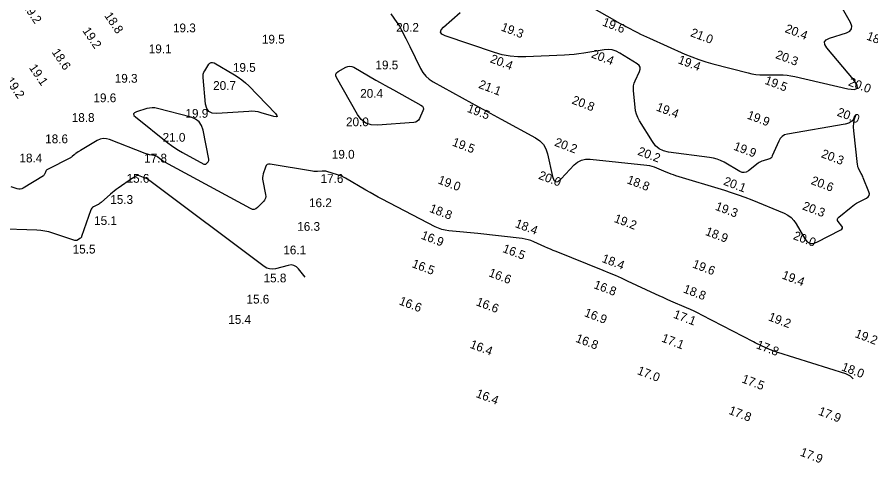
# Model space of a CAD drawing. Extents: x 824616 to 827440, y 158441 to 163197.
# Drawn here: x 826605.2 to 827092.4, y 159619.4 to 159873.5 of the extents above; entities that cross this region are included whole.
import ezdxf

# ---------------------------------------------------------------- set-up
doc = ezdxf.new("R2010")
doc.units = 0
for name, color, linetype in [('V-CHAN-CONT-EL16', 7, 'Continuous'), ('V-CHAN-CONT-EL18', 7, 'Continuous'), ('V-CHAN-CONT-EL20', 7, 'Continuous'), ('V-TOPO-SOUN', 7, 'Continuous')]:
    doc.layers.add(name, color=color, linetype=linetype)

msp = doc.modelspace()

# ---------------------------------------------------------------- linework, layer by layer
at = {"layer": 'V-CHAN-CONT-EL16'}
msp.add_lwpolyline([(826769.52, 159725.22), (826765.77, 159730.04), (826764.54, 159731.26), (826763.16, 159732), (826761.61, 159732.25), (826759.89, 159732.02), (826752.71, 159730.11), (826750.95, 159729.84), (826749.27, 159729.96), (826747.67, 159730.47), (826746.15, 159731.39), (826680.92, 159780.28), (826680.29, 159780.72), (826679.63, 159781.12), (826678.96, 159781.46), (826678.25, 159781.77), (826674.57, 159783.2), (826674.26, 159783.29), (826673.97, 159783.3), (826673.67, 159783.24), (826673.39, 159783.11), (826672.26, 159782.45), (826671.98, 159782.28), (826671.7, 159782.1), (826671.42, 159781.92), (826671.15, 159781.74), (826662.92, 159776.01), (826661.78, 159775.19), (826660.67, 159774.34), (826659.57, 159773.47), (826658.5, 159772.56), (826653.1, 159767.85), (826652.62, 159767.46), (826652.11, 159767.09), (826651.59, 159766.76), (826651.04, 159766.47), (826648.81, 159765.34), (826648.29, 159765.02), (826647.86, 159764.62), (826647.53, 159764.14), (826647.28, 159763.59), (826642.04, 159748.49), (826641.88, 159748.13), (826641.67, 159747.81), (826641.41, 159747.53), (826641.09, 159747.3), (826639.71, 159746.45), (826639.37, 159746.28), (826639.01, 159746.19), (826638.64, 159746.19), (826638.26, 159746.27), (826625.61, 159750.41), (826623.36, 159751.07), (826621.08, 159751.56), (826618.78, 159751.89), (826616.44, 159752.06), (826593.19, 159752.93)], dxfattribs=at)
at = {"layer": 'V-CHAN-CONT-EL18'}
msp.add_lwpolyline([(827082.22, 159667.32), (827080.8, 159668.89), (827077.96, 159670.24), (827039.28, 159682.33), (827038.07, 159682.73), (827036.88, 159683.16), (827035.69, 159683.62), (827034.52, 159684.11), (827029.87, 159686.16), (827028.71, 159686.68), (827027.55, 159687.22), (827026.41, 159687.78), (827025.28, 159688.36), (826995.94, 159703.69), (826993.78, 159704.79), (826991.6, 159705.86), (826989.4, 159706.87), (826987.18, 159707.85), (826978.27, 159711.68), (826976.04, 159712.65), (826973.82, 159713.63), (826971.61, 159714.63), (826969.41, 159715.65), (826953.43, 159723.1), (826950.02, 159724.66), (826946.59, 159726.17), (826943.14, 159727.64), (826939.68, 159729.06), (826912.76, 159739.87), (826911.14, 159740.53), (826909.54, 159741.2), (826907.94, 159741.89), (826906.34, 159742.6), (826899.99, 159745.46), (826898.38, 159746.11), (826896.74, 159746.63), (826895.06, 159747.02), (826893.35, 159747.28), (826868.08, 159750.12), (826866.01, 159750.34), (826863.95, 159750.56), (826861.88, 159750.77), (826859.82, 159750.96), (826851.55, 159751.72), (826849.51, 159752.01), (826847.53, 159752.49), (826845.6, 159753.16), (826843.74, 159754.02), (826813.6, 159769.72), (826811.24, 159770.96), (826808.89, 159772.24), (826806.57, 159773.54), (826804.26, 159774.87), (826792.64, 159781.66), (826791.52, 159782.27), (826790.38, 159782.81), (826789.2, 159783.28), (826787.99, 159783.67), (826781.98, 159785.45), (826781.31, 159785.62), (826780.64, 159785.72), (826779.96, 159785.77), (826779.28, 159785.75), (826776.53, 159785.56), (826775.84, 159785.53), (826775.15, 159785.54), (826774.47, 159785.59), (826773.79, 159785.69), (826749.61, 159789.66), (826748.68, 159789.68), (826747.92, 159789.42), (826747.34, 159788.87), (826746.94, 159788.03), (826745.66, 159784.11), (826745.41, 159783.13), (826745.29, 159782.13), (826745.29, 159781.14), (826745.43, 159780.13), (826746.96, 159772.46), (826747.06, 159771.31), (826746.89, 159770.25), (826746.45, 159769.26), (826745.73, 159768.36), (826742.32, 159764.91), (826741.44, 159764.23), (826740.5, 159763.9), (826739.52, 159763.94), (826738.48, 159764.34), (826689.57, 159790.79), (826689.03, 159791.1), (826688.51, 159791.43), (826688, 159791.78), (826687.51, 159792.15), (826685.58, 159793.69), (826685.08, 159794.04), (826684.54, 159794.32), (826683.98, 159794.52), (826683.39, 159794.65), (826680.81, 159795.07), (826680.18, 159795.18), (826679.56, 159795.33), (826678.95, 159795.52), (826678.35, 159795.73), (826658, 159803.68), (826656.18, 159804.18), (826654.4, 159804.26), (826652.65, 159803.9), (826650.93, 159803.12), (826641.42, 159797.53), (826641.08, 159797.33), (826640.75, 159797.12), (826640.43, 159796.91), (826640.11, 159796.69), (826638.72, 159795.72), (826638.46, 159795.54), (826638.2, 159795.34), (826637.95, 159795.14), (826637.7, 159794.93), (826636.72, 159794.08), (826636.47, 159793.87), (826636.21, 159793.69), (826635.94, 159793.52), (826635.66, 159793.36), (826622.51, 159786.72), (826622.2, 159786.53), (826621.95, 159786.29), (826621.74, 159786), (826621.59, 159785.67), (826621.1, 159784.25), (826620.95, 159783.91), (826620.76, 159783.62), (826620.51, 159783.36), (826620.22, 159783.14), (826608.64, 159775.99), (826607.86, 159775.6), (826607.04, 159775.41), (826606.21, 159775.41), (826605.35, 159775.6), (826601.88, 159776.73)], dxfattribs=at)
at = {"layer": 'V-CHAN-CONT-EL20'}
for points in [[(826928.5, 159881.59), (826946.03, 159871.75), (826947.67, 159870.84), (826949.31, 159869.94), (826950.96, 159869.05), (826952.61, 159868.18), (826959.25, 159864.72), (826960.92, 159863.87), (826962.6, 159863.04), (826964.29, 159862.24), (826965.99, 159861.47), (826986.27, 159852.45), (826990.16, 159850.82), (826994.1, 159849.35), (826998.09, 159848.05), (827002.15, 159846.91), (827022.31, 159841.69), (827024.49, 159841.2), (827026.68, 159840.85), (827028.89, 159840.65), (827031.12, 159840.6), (827040.08, 159840.66), (827042.31, 159840.62), (827044.53, 159840.44), (827046.73, 159840.13), (827048.92, 159839.69), (827079.27, 159832.7), (827082.97, 159832.22), (827084.74, 159832.93), (827084.56, 159834.82), (827082.44, 159837.9), (827067.17, 159856.07), (827066.05, 159857.86), (827065.94, 159859.35), (827066.83, 159860.56), (827068.74, 159861.47), (827078.37, 159864.53), (827080.33, 159865.47), (827081.36, 159866.77), (827081.49, 159868.43), (827080.7, 159870.45), (827070.98, 159887.58)], [(826818.41, 159875.36), (826821.9, 159870.54), (826822.65, 159869.47), (826823.36, 159868.36), (826824.02, 159867.23), (826824.63, 159866.07), (826827.01, 159861.38), (826827.6, 159860.21), (826828.19, 159859.03), (826828.77, 159857.86), (826829.35, 159856.68), (826835.41, 159844.21), (826836.76, 159841.89), (826838.41, 159839.84), (826840.37, 159838.09), (826842.62, 159836.62), (826864.62, 159824.51), (826868.8, 159822.21), (826872.98, 159819.92), (826877.17, 159817.64), (826881.37, 159815.37), (826901.05, 159804.75), (826903.54, 159803.07), (826905.51, 159800.99), (826906.95, 159798.52), (826907.87, 159795.67), (826910.69, 159782.65), (826911.43, 159780.57), (826912.48, 159779.65), (826913.86, 159779.89), (826915.56, 159781.3), (826923, 159789.23), (826924.96, 159790.93), (826927.14, 159792.06), (826929.52, 159792.62), (826932.12, 159792.61), (826964.5, 159789.09), (826965.94, 159788.88), (826967.35, 159788.56), (826968.73, 159788.14), (826970.08, 159787.61), (826975.43, 159785.28), (826976.78, 159784.72), (826978.14, 159784.2), (826979.51, 159783.72), (826980.9, 159783.28), (827008.77, 159774.84), (827012.71, 159773.6), (827016.62, 159772.26), (827020.5, 159770.83), (827024.34, 159769.3), (827042.77, 159761.74), (827044.9, 159760.67), (827046.78, 159759.29), (827048.4, 159757.62), (827049.76, 159755.65), (827054.69, 159747.18), (827056.05, 159745.47), (827057.63, 159744.57), (827059.46, 159744.48), (827061.51, 159745.19), (827075.25, 159752.27), (827075.83, 159752.69), (827076.1, 159753.18), (827076.07, 159753.73), (827075.72, 159754.36), (827073.71, 159757.01), (827073.35, 159757.66), (827073.27, 159758.27), (827073.49, 159758.85), (827073.98, 159759.4), (827081.03, 159765.24), (827082.03, 159766.03), (827083.08, 159766.77), (827084.17, 159767.44), (827085.29, 159768.05), (827089.86, 159770.39), (827090.8, 159771.05), (827091.34, 159771.86), (827091.47, 159772.83), (827091.19, 159773.94), (827087.96, 159781.99), (827087.69, 159782.62), (827087.41, 159783.25), (827087.11, 159783.86), (827086.8, 159784.47), (827085.5, 159786.89), (827085.21, 159787.51), (827084.98, 159788.14), (827084.82, 159788.79), (827084.71, 159789.46), (827082.62, 159808.76), (827082.5, 159811.03), (827082.65, 159813.26), (827083.07, 159815.47), (827083.74, 159817.63), (827082.75, 159815.7), (827081.39, 159814.21), (827079.67, 159813.16), (827077.59, 159812.54), (827044.79, 159806.85), (827043.13, 159806.37), (827041.75, 159805.55), (827040.63, 159804.39), (827039.77, 159802.89), (827036.1, 159794.37), (827035.73, 159793.69), (827035.24, 159793.15), (827034.64, 159792.74), (827033.92, 159792.46), (827030.83, 159791.6), (827030.08, 159791.34), (827029.36, 159791.03), (827028.67, 159790.64), (827028.02, 159790.18), (827022.42, 159785.87), (827021.26, 159785.19), (827020.08, 159784.91), (827018.87, 159785.03), (827017.63, 159785.56), (827008.59, 159790.78), (827006.63, 159791.79), (827004.6, 159792.59), (827002.51, 159793.19), (827000.34, 159793.58), (826976.93, 159796.62), (826974.1, 159797.28), (826971.63, 159798.49), (826969.51, 159800.24), (826967.74, 159802.55), (826960.37, 159814.49), (826959.39, 159816.29), (826958.64, 159818.16), (826958.11, 159820.1), (826957.79, 159822.12), (826956.87, 159831.51), (826956.82, 159832.97), (826956.97, 159834.4), (826957.3, 159835.8), (826957.83, 159837.16), (826960.32, 159842.55), (826960.7, 159843.83), (826960.62, 159844.97), (826960.07, 159845.96), (826959.05, 159846.82), (826949.12, 159853.05), (826947.01, 159854.14), (826944.8, 159854.81), (826942.52, 159855.05), (826940.14, 159854.88), (826928.52, 159853.02), (826925.77, 159852.62), (826923.02, 159852.3), (826920.25, 159852.05), (826917.48, 159851.88), (826895.51, 159850.82), (826890.95, 159850.81), (826886.45, 159851.22), (826882.01, 159852.06), (826877.63, 159853.31), (826849.44, 159862.82), (826847.57, 159863.73), (826846.79, 159864.86), (826847.08, 159866.21), (826848.46, 159867.77), (826858.04, 159876.1)]]:
    msp.add_lwpolyline(points, dxfattribs=at)
for points in [[(826711.46, 159841.09), (826711.78, 159842.06), (826712.27, 159842.99), (826714.56, 159846.63), (826715.18, 159847.36), (826715.88, 159847.73), (826716.68, 159847.73), (826717.57, 159847.38), (826729.23, 159840.65), (826731.42, 159839.28), (826733.51, 159837.76), (826735.48, 159836.11), (826737.35, 159834.31), (826752.58, 159818.54), (826753.48, 159817.45), (826753.61, 159816.82), (826752.99, 159816.65), (826751.61, 159816.94), (826744.56, 159819.02), (826742.79, 159819.46), (826741, 159819.74), (826739.19, 159819.86), (826737.37, 159819.81), (826719.11, 159818.54), (826716.55, 159818.73), (826714.64, 159819.68), (826713.39, 159821.41), (826712.78, 159823.9), (826711.33, 159839.03), (826711.31, 159840.08)], [(826787.01, 159841.03), (826787.48, 159841.83), (826788.38, 159842.51), (826792.86, 159844.98), (826793.98, 159845.44), (826795.09, 159845.59), (826796.21, 159845.42), (826797.31, 159844.93), (826809.97, 159837.61), (826812.45, 159836.18), (826814.94, 159834.77), (826817.44, 159833.37), (826819.94, 159831.98), (826835.61, 159823.35), (826836.45, 159822.72), (826836.91, 159821.97), (826837, 159821.09), (826836.71, 159820.08), (826834.83, 159815.81), (826834.27, 159814.86), (826833.54, 159814.16), (826832.63, 159813.7), (826831.55, 159813.49), (826810.86, 159811.91), (826807.26, 159812.07), (826804.15, 159813.14), (826801.52, 159815.12), (826799.37, 159818.01), (826787.4, 159839.05), (826786.99, 159840.1)], [(826682.36, 159821.84), (826680.84, 159821.7), (826679.33, 159821.35), (826673.3, 159819.5), (826672.13, 159818.97), (826671.65, 159818.32), (826671.86, 159817.53), (826672.75, 159816.61), (826691.31, 159801.86), (826693.28, 159800.37), (826695.3, 159798.97), (826697.38, 159797.66), (826699.52, 159796.44), (826711.85, 159789.77), (826712.19, 159789.64), (826712.52, 159789.63), (826712.83, 159789.74), (826713.13, 159789.96), (826714.26, 159791.11), (826714.5, 159791.41), (826714.65, 159791.74), (826714.71, 159792.1), (826714.67, 159792.48), (826711.35, 159809.11), (826710.49, 159811.75), (826709.05, 159813.84), (826707.05, 159815.41), (826704.47, 159816.43), (826685.4, 159821.47), (826683.88, 159821.76)]]:
    msp.add_lwpolyline(points, close=True, dxfattribs=at)

# ---------------------------------------------------------------- texts
at = {"layer": 'V-TOPO-SOUN'}
for s, rotation, p in [('19.2 ', 304.2, (826608.19, 159879.97)), ('18.8 ', 304.2, (826654.78, 159874.32)), ('19.6 ', 339.2, (826938.74, 159868.84)), ('19.2 ', 304.2, (826642.32, 159865.73)), ('19.3 ', 339.2, (826880.92, 159865.98)), ('21.0 ', 339.2, (826988.99, 159862.77)), ('20.4 ', 339.2, (827042.94, 159865.07)), ('18.8 ', 339.2, (827089.46, 159860.83)), ('18.6 ', 304.2, (826624.78, 159853.56)), ('20.4 ', 339.2, (826874.74, 159847.86)), ('20.4 ', 339.2, (826932.41, 159850.64)), ('19.4 ', 339.2, (826981.91, 159847.33)), ('20.3 ', 339.2, (827037.53, 159850.27)), ('19.1 ', 304.2, (826611.81, 159844.7)), ('19.2 ', 304.2, (826598.49, 159837.31)), ('21.1 ', 339.2, (826868.13, 159833.29)), ('19.5 ', 339.2, (827031.38, 159835.6)), ('20.0 ', 339.2, (827079.09, 159834.69)), ('20.8 ', 339.2, (826921.36, 159824.34)), ('19.5 ', 339.2, (826861.55, 159819.64)), ('19.4 ', 339.2, (826969.47, 159820.38)), ('19.9 ', 339.2, (827021.29, 159815.81)), ('20.0 ', 339.2, (827072.59, 159817.47)), ('19.5 ', 339.2, (826853.06, 159800.4)), ('20.2 ', 339.2, (826911.45, 159800.33)), ('20.2 ', 339.2, (826958.92, 159795.16)), ('19.9 ', 339.2, (827013.63, 159798.03)), ('20.3 ', 339.2, (827063.61, 159793.76)), ('20.0 ', 339.2, (826902.31, 159781.47)), ('19.0 ', 339.2, (826844.93, 159778.85)), ('18.8 ', 339.2, (826952.74, 159778.92)), ('20.1 ', 339.2, (827007.84, 159778.11)), ('20.6 ', 339.2, (827057.74, 159778.49)), ('18.8 ', 339.2, (826840.09, 159762.61)), ('19.3 ', 339.2, (827003.14, 159763.8)), ('20.3 ', 339.2, (827052.88, 159764.02)), ('19.2 ', 339.2, (826945.42, 159756.87)), ('18.4 ', 339.2, (826888.96, 159753.95)), ('16.9 ', 339.2, (826835.31, 159747.32)), ('18.9 ', 339.2, (826997.51, 159749.46)), ('20.0 ', 339.2, (827047.63, 159747.09)), ('16.5 ', 339.2, (826881.85, 159739.73)), ('16.5 ', 339.2, (826830.09, 159731.1)), ('18.4 ', 339.2, (826938.44, 159734.07)), ('19.6 ', 339.2, (826990.14, 159730.93)), ('16.6 ', 339.2, (826873.87, 159725.92)), ('19.4 ', 339.2, (827041.19, 159724.64)), ('16.8 ', 339.2, (826933.82, 159719.12)), ('18.8 ', 339.2, (826984.9, 159716.7)), ('16.6 ', 339.2, (826822.76, 159709.86)), ('16.6 ', 339.2, (826866.7, 159709.37)), ('16.9 ', 339.2, (826928.44, 159703.17)), ('17.1 ', 339.2, (826979.26, 159702.26)), ('19.2 ', 339.2, (827033.44, 159700.79)), ('16.8 ', 339.2, (826923.48, 159688.55)), ('17.1 ', 339.2, (826972.49, 159688.71)), ('19.2 ', 339.2, (827082.84, 159691.24)), ('16.4 ', 339.2, (826863.21, 159685.14)), ('17.8 ', 339.2, (827026.52, 159684.89)), ('18.0 ', 339.2, (827075.18, 159672.27)), ('17.0 ', 339.2, (826958.64, 159670.15)), ('17.5 ', 339.2, (827018.27, 159665.42)), ('16.4 ', 339.2, (826866.61, 159657.1)), ('17.8 ', 339.2, (827010.83, 159647.47)), ('17.9 ', 339.2, (827061.96, 159647.01)), ('17.9 ', 339.2, (827051.56, 159623.7))]:
    msp.add_text(s, height=5, rotation=rotation, dxfattribs=at).set_placement(p)
for s, p in [('19.3 ', (826694.15, 159864.86)), ('20.2 ', (826821.48, 159865.16)), ('19.5 ', (826744.89, 159858.45)), ('19.1 ', (826680.34, 159852.91)), ('19.5 ', (826728.35, 159842.34)), ('19.5 ', (826809.66, 159843.74)), ('19.3 ', (826660.93, 159836.12)), ('20.7 ', (826717.08, 159832.04)), ('20.4 ', (826800.98, 159827.54)), ('19.6 ', (826648.78, 159825.01)), ('18.8 ', (826636.4, 159813.78)), ('19.9 ', (826701.28, 159816.16)), ('20.0 ', (826792.89, 159811.32)), ('21.0 ', (826688.24, 159802.49)), ('18.6 ', (826621.26, 159801.64)), ('19.0 ', (826784.79, 159792.83)), ('18.4 ', (826606.57, 159790.7)), ('17.8 ', (826677.73, 159790.64)), ('15.6 ', (826667.68, 159779.11)), ('17.6 ', (826778.38, 159779)), ('15.3 ', (826658.38, 159767.07)), ('16.2 ', (826771.77, 159765.2)), ('15.1 ', (826649.17, 159755.05)), ('16.3 ', (826765.06, 159751.72)), ('15.5 ', (826636.94, 159738.77)), ('16.1 ', (826757.11, 159738.29)), ('15.8 ', (826745.85, 159722.33)), ('15.6 ', (826736.11, 159710.27)), ('15.4 ', (826725.7, 159698.66))]:
    msp.add_text(s, height=5, dxfattribs=at).set_placement(p)

doc.saveas('drawing.dxf')
